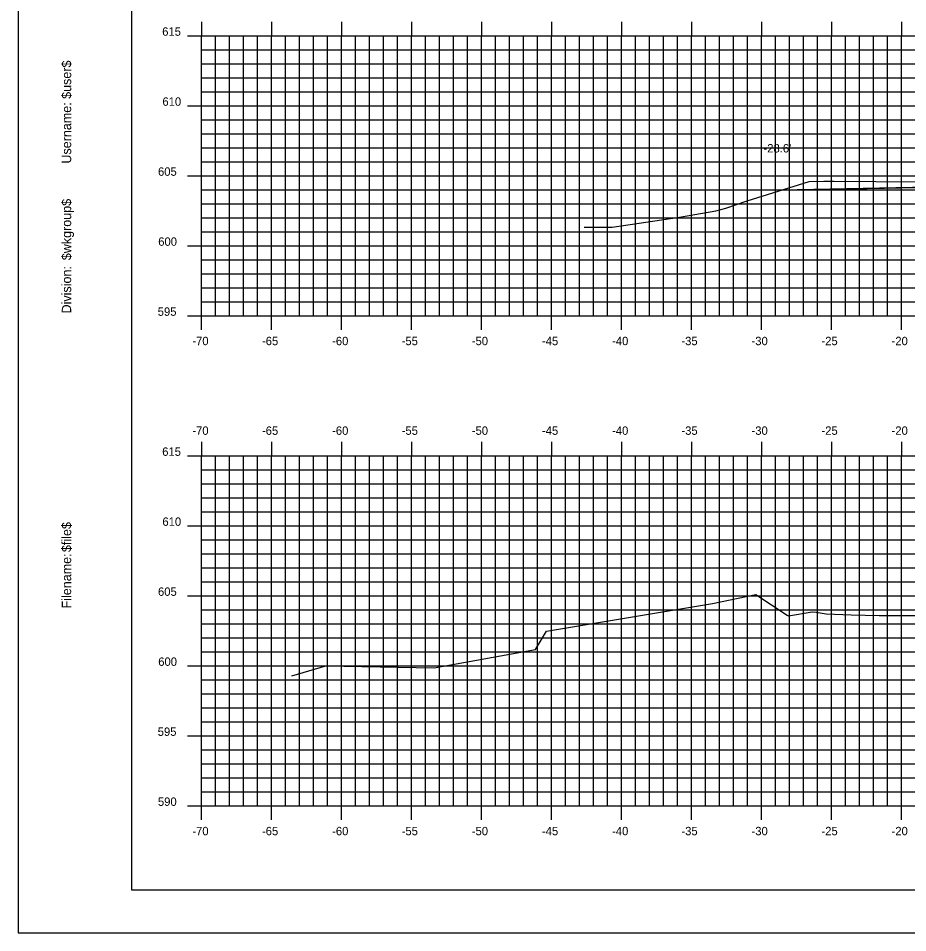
# Model space of a CAD drawing. Extents: x 1048362 to 1048532, y 780904 to 781014.
# Drawn here: x 1048362.4 to 1048425.9, y 780904.1 to 780969.4 of the extents above; entities that cross this region are included whole.
import ezdxf

# ---------------------------------------------------------------- set-up
doc = ezdxf.new("R2010")
doc.units = 0
for name, color, linetype in [('ANNOTATION', 7, 'Continuous'), ('D_Roadway_Centerline', 7, 'Continuous'), ('D_Roadway_SlopeLines', 7, 'Continuous'), ('Default', 7, 'Continuous'), ('H_V ANNOTATION', 7, 'Continuous'), ('MAJOR', 7, 'Continuous'), ('MINOR', 7, 'Continuous'), ('S_Roadway_Centerline', 7, 'Continuous')]:
    doc.layers.add(name, color=color, linetype=linetype)

msp = doc.modelspace()

# ---------------------------------------------------------------- linework, layer by layer
at = {"layer": 'D_Roadway_Centerline'}
msp.add_lwpolyline([(1048416.852, 780957.079), (1048434.112, 780957.424), (1048445.469, 780957.651), (1048479.364, 780956.973), (1048491.458, 780956.731)], dxfattribs=at)
at = {"layer": 'D_Roadway_SlopeLines'}
msp.add_line((1048434.112, 780957.424), (1048416.852, 780957.079), dxfattribs=at)
at = {"layer": 'Default'}
for p, q in [((1048370.47, 781012.114), (1048370.47, 780907.114)), ((1048370.47, 780907.114), (1048530.47, 780907.114))]:
    msp.add_line(p, q, dxfattribs=at)
msp.add_lwpolyline([(1048362.376, 780904.055), (1048532.376, 780904.055), (1048532.376, 781014.055), (1048362.376, 781014.055)], close=True, dxfattribs=at)
at = {"layer": 'MAJOR'}
for p, q in [((1048375.469, 780969.116), (1048375.469, 780968.114)), ((1048380.469, 780969.116), (1048380.469, 780968.114)), ((1048385.469, 780969.116), (1048385.469, 780968.114)), ((1048390.469, 780969.116), (1048390.469, 780968.114)), ((1048395.469, 780969.116), (1048395.469, 780968.114)), ((1048400.469, 780969.116), (1048400.469, 780968.114)), ((1048405.469, 780969.116), (1048405.469, 780968.114)), ((1048410.469, 780969.116), (1048410.469, 780968.114)), ((1048415.469, 780969.116), (1048415.469, 780968.114)), ((1048420.469, 780969.116), (1048420.469, 780968.114)), ((1048425.469, 780969.116), (1048425.469, 780968.114)), ((1048374.467, 780968.114), (1048375.469, 780968.114)), ((1048375.469, 780968.114), (1048515.469, 780968.114)), ((1048375.469, 780948.114), (1048375.469, 780968.114)), ((1048375.469, 780948.114), (1048375.469, 780968.114)), ((1048375.469, 780968.114), (1048515.469, 780968.114)), ((1048380.469, 780948.114), (1048380.469, 780968.114)), ((1048385.469, 780948.114), (1048385.469, 780968.114)), ((1048390.469, 780948.114), (1048390.469, 780968.114)), ((1048395.469, 780948.114), (1048395.469, 780968.114)), ((1048400.469, 780948.114), (1048400.469, 780968.114)), ((1048405.469, 780948.114), (1048405.469, 780968.114)), ((1048410.469, 780948.114), (1048410.469, 780968.114)), ((1048415.469, 780948.114), (1048415.469, 780968.114)), ((1048420.469, 780948.114), (1048420.469, 780968.114)), ((1048425.469, 780948.114), (1048425.469, 780968.114)), ((1048374.467, 780963.114), (1048375.469, 780963.114)), ((1048375.469, 780963.114), (1048515.469, 780963.114)), ((1048374.467, 780958.114), (1048375.469, 780958.114)), ((1048375.469, 780958.114), (1048515.469, 780958.114)), ((1048374.467, 780953.114), (1048375.469, 780953.114)), ((1048375.469, 780953.114), (1048515.469, 780953.114)), ((1048374.467, 780948.114), (1048375.469, 780948.114)), ((1048375.469, 780948.114), (1048515.469, 780948.114)), ((1048375.469, 780948.114), (1048515.469, 780948.114)), ((1048375.469, 780947.112), (1048375.469, 780948.114)), ((1048380.469, 780947.112), (1048380.469, 780948.114)), ((1048385.469, 780947.112), (1048385.469, 780948.114)), ((1048390.469, 780947.112), (1048390.469, 780948.114)), ((1048395.469, 780947.112), (1048395.469, 780948.114)), ((1048400.469, 780947.112), (1048400.469, 780948.114)), ((1048405.469, 780947.112), (1048405.469, 780948.114)), ((1048410.469, 780947.112), (1048410.469, 780948.114)), ((1048415.469, 780947.112), (1048415.469, 780948.114)), ((1048420.469, 780947.112), (1048420.469, 780948.114)), ((1048425.469, 780947.112), (1048425.469, 780948.114)), ((1048375.469, 780939.116), (1048375.469, 780938.114)), ((1048380.469, 780939.116), (1048380.469, 780938.114)), ((1048385.469, 780939.116), (1048385.469, 780938.114)), ((1048390.469, 780939.116), (1048390.469, 780938.114)), ((1048395.469, 780939.116), (1048395.469, 780938.114)), ((1048400.469, 780939.116), (1048400.469, 780938.114)), ((1048405.469, 780939.116), (1048405.469, 780938.114)), ((1048410.469, 780939.116), (1048410.469, 780938.114)), ((1048415.469, 780939.116), (1048415.469, 780938.114)), ((1048420.469, 780939.116), (1048420.469, 780938.114)), ((1048425.469, 780939.116), (1048425.469, 780938.114)), ((1048374.467, 780938.114), (1048375.469, 780938.114)), ((1048375.469, 780938.114), (1048515.469, 780938.114)), ((1048375.469, 780913.114), (1048375.469, 780938.114)), ((1048375.469, 780913.114), (1048375.469, 780938.114)), ((1048375.469, 780938.114), (1048515.469, 780938.114)), ((1048380.469, 780913.114), (1048380.469, 780938.114)), ((1048385.469, 780913.114), (1048385.469, 780938.114)), ((1048390.469, 780913.114), (1048390.469, 780938.114)), ((1048395.469, 780913.114), (1048395.469, 780938.114)), ((1048400.469, 780913.114), (1048400.469, 780938.114)), ((1048405.469, 780913.114), (1048405.469, 780938.114)), ((1048410.469, 780913.114), (1048410.469, 780938.114)), ((1048415.469, 780913.114), (1048415.469, 780938.114)), ((1048420.469, 780913.114), (1048420.469, 780938.114)), ((1048425.469, 780913.114), (1048425.469, 780938.114)), ((1048374.467, 780933.114), (1048375.469, 780933.114)), ((1048375.469, 780933.114), (1048515.469, 780933.114)), ((1048374.467, 780928.114), (1048375.469, 780928.114)), ((1048375.469, 780928.114), (1048515.469, 780928.114)), ((1048374.467, 780923.114), (1048375.469, 780923.114)), ((1048375.469, 780923.114), (1048515.469, 780923.114)), ((1048374.467, 780918.114), (1048375.469, 780918.114)), ((1048375.469, 780918.114), (1048515.469, 780918.114)), ((1048374.467, 780913.114), (1048375.469, 780913.114)), ((1048375.469, 780913.114), (1048515.469, 780913.114)), ((1048375.469, 780913.114), (1048515.469, 780913.114)), ((1048375.469, 780912.112), (1048375.469, 780913.114)), ((1048380.469, 780912.112), (1048380.469, 780913.114)), ((1048385.469, 780912.112), (1048385.469, 780913.114)), ((1048390.469, 780912.112), (1048390.469, 780913.114)), ((1048395.469, 780912.112), (1048395.469, 780913.114)), ((1048400.469, 780912.112), (1048400.469, 780913.114)), ((1048405.469, 780912.112), (1048405.469, 780913.114)), ((1048410.469, 780912.112), (1048410.469, 780913.114)), ((1048415.469, 780912.112), (1048415.469, 780913.114)), ((1048420.469, 780912.112), (1048420.469, 780913.114)), ((1048425.469, 780912.112), (1048425.469, 780913.114))]:
    msp.add_line(p, q, dxfattribs=at)
at = {"layer": 'MINOR'}
for p, q in [((1048376.469, 780948.114), (1048376.469, 780968.114)), ((1048377.469, 780948.114), (1048377.469, 780968.114)), ((1048378.469, 780948.114), (1048378.469, 780968.114)), ((1048379.469, 780948.114), (1048379.469, 780968.114)), ((1048381.469, 780948.114), (1048381.469, 780968.114)), ((1048382.469, 780948.114), (1048382.469, 780968.114)), ((1048383.469, 780948.114), (1048383.469, 780968.114)), ((1048384.469, 780948.114), (1048384.469, 780968.114)), ((1048386.469, 780948.114), (1048386.469, 780968.114)), ((1048387.469, 780948.114), (1048387.469, 780968.114)), ((1048388.469, 780948.114), (1048388.469, 780968.114)), ((1048389.469, 780948.114), (1048389.469, 780968.114)), ((1048391.469, 780948.114), (1048391.469, 780968.114)), ((1048392.469, 780948.114), (1048392.469, 780968.114)), ((1048393.469, 780948.114), (1048393.469, 780968.114)), ((1048394.469, 780948.114), (1048394.469, 780968.114)), ((1048396.469, 780948.114), (1048396.469, 780968.114)), ((1048397.469, 780948.114), (1048397.469, 780968.114)), ((1048398.469, 780948.114), (1048398.469, 780968.114)), ((1048399.469, 780948.114), (1048399.469, 780968.114)), ((1048401.469, 780948.114), (1048401.469, 780968.114)), ((1048402.469, 780948.114), (1048402.469, 780968.114)), ((1048403.469, 780948.114), (1048403.469, 780968.114)), ((1048404.469, 780948.114), (1048404.469, 780968.114)), ((1048406.469, 780948.114), (1048406.469, 780968.114)), ((1048407.469, 780948.114), (1048407.469, 780968.114)), ((1048408.469, 780948.114), (1048408.469, 780968.114)), ((1048409.469, 780948.114), (1048409.469, 780968.114)), ((1048411.469, 780948.114), (1048411.469, 780968.114)), ((1048412.469, 780948.114), (1048412.469, 780968.114)), ((1048413.469, 780948.114), (1048413.469, 780968.114)), ((1048414.469, 780948.114), (1048414.469, 780968.114)), ((1048416.469, 780948.114), (1048416.469, 780968.114)), ((1048417.469, 780948.114), (1048417.469, 780968.114)), ((1048418.469, 780948.114), (1048418.469, 780968.114)), ((1048419.469, 780948.114), (1048419.469, 780968.114)), ((1048421.469, 780948.114), (1048421.469, 780968.114)), ((1048422.469, 780948.114), (1048422.469, 780968.114)), ((1048423.469, 780948.114), (1048423.469, 780968.114)), ((1048424.469, 780948.114), (1048424.469, 780968.114)), ((1048375.469, 780967.114), (1048515.469, 780967.114)), ((1048375.469, 780967.114), (1048376.471, 780967.114)), ((1048375.469, 780966.114), (1048515.469, 780966.114)), ((1048375.469, 780966.114), (1048376.471, 780966.114)), ((1048375.469, 780965.114), (1048515.469, 780965.114)), ((1048375.469, 780965.114), (1048376.471, 780965.114)), ((1048375.469, 780964.114), (1048515.469, 780964.114)), ((1048375.469, 780964.114), (1048376.471, 780964.114)), ((1048375.469, 780962.114), (1048515.469, 780962.114)), ((1048375.469, 780962.114), (1048376.471, 780962.114)), ((1048375.469, 780961.114), (1048515.469, 780961.114)), ((1048375.469, 780961.114), (1048376.471, 780961.114)), ((1048375.469, 780960.114), (1048515.469, 780960.114)), ((1048375.469, 780960.114), (1048376.471, 780960.114)), ((1048375.469, 780959.114), (1048515.469, 780959.114)), ((1048375.469, 780959.114), (1048376.471, 780959.114)), ((1048375.469, 780957.114), (1048515.469, 780957.114)), ((1048375.469, 780957.114), (1048376.471, 780957.114)), ((1048375.469, 780956.114), (1048515.469, 780956.114)), ((1048375.469, 780956.114), (1048376.471, 780956.114)), ((1048375.469, 780955.114), (1048515.469, 780955.114)), ((1048375.469, 780955.114), (1048376.471, 780955.114)), ((1048375.469, 780954.114), (1048515.469, 780954.114)), ((1048375.469, 780954.114), (1048376.471, 780954.114)), ((1048375.469, 780952.114), (1048515.469, 780952.114)), ((1048375.469, 780952.114), (1048376.471, 780952.114)), ((1048375.469, 780951.114), (1048515.469, 780951.114)), ((1048375.469, 780951.114), (1048376.471, 780951.114)), ((1048375.469, 780950.114), (1048515.469, 780950.114)), ((1048375.469, 780950.114), (1048376.471, 780950.114)), ((1048375.469, 780949.114), (1048515.469, 780949.114)), ((1048375.469, 780949.114), (1048376.471, 780949.114)), ((1048376.469, 780913.114), (1048376.469, 780938.114)), ((1048377.469, 780913.114), (1048377.469, 780938.114)), ((1048378.469, 780913.114), (1048378.469, 780938.114)), ((1048379.469, 780913.114), (1048379.469, 780938.114)), ((1048381.469, 780913.114), (1048381.469, 780938.114)), ((1048382.469, 780913.114), (1048382.469, 780938.114)), ((1048383.469, 780913.114), (1048383.469, 780938.114)), ((1048384.469, 780913.114), (1048384.469, 780938.114)), ((1048386.469, 780913.114), (1048386.469, 780938.114)), ((1048387.469, 780913.114), (1048387.469, 780938.114)), ((1048388.469, 780913.114), (1048388.469, 780938.114)), ((1048389.469, 780913.114), (1048389.469, 780938.114)), ((1048391.469, 780913.114), (1048391.469, 780938.114)), ((1048392.469, 780913.114), (1048392.469, 780938.114)), ((1048393.469, 780913.114), (1048393.469, 780938.114)), ((1048394.469, 780913.114), (1048394.469, 780938.114)), ((1048396.469, 780913.114), (1048396.469, 780938.114)), ((1048397.469, 780913.114), (1048397.469, 780938.114)), ((1048398.469, 780913.114), (1048398.469, 780938.114)), ((1048399.469, 780913.114), (1048399.469, 780938.114)), ((1048401.469, 780913.114), (1048401.469, 780938.114)), ((1048402.469, 780913.114), (1048402.469, 780938.114)), ((1048403.469, 780913.114), (1048403.469, 780938.114)), ((1048404.469, 780913.114), (1048404.469, 780938.114)), ((1048406.469, 780913.114), (1048406.469, 780938.114)), ((1048407.469, 780913.114), (1048407.469, 780938.114)), ((1048408.469, 780913.114), (1048408.469, 780938.114)), ((1048409.469, 780913.114), (1048409.469, 780938.114)), ((1048411.469, 780913.114), (1048411.469, 780938.114)), ((1048412.469, 780913.114), (1048412.469, 780938.114)), ((1048413.469, 780913.114), (1048413.469, 780938.114)), ((1048414.469, 780913.114), (1048414.469, 780938.114)), ((1048416.469, 780913.114), (1048416.469, 780938.114)), ((1048417.469, 780913.114), (1048417.469, 780938.114)), ((1048418.469, 780913.114), (1048418.469, 780938.114)), ((1048419.469, 780913.114), (1048419.469, 780938.114)), ((1048421.469, 780913.114), (1048421.469, 780938.114)), ((1048422.469, 780913.114), (1048422.469, 780938.114)), ((1048423.469, 780913.114), (1048423.469, 780938.114)), ((1048424.469, 780913.114), (1048424.469, 780938.114)), ((1048375.469, 780937.114), (1048515.469, 780937.114)), ((1048375.469, 780937.114), (1048376.471, 780937.114)), ((1048375.469, 780936.114), (1048515.469, 780936.114)), ((1048375.469, 780936.114), (1048376.471, 780936.114)), ((1048375.469, 780935.114), (1048515.469, 780935.114)), ((1048375.469, 780935.114), (1048376.471, 780935.114)), ((1048375.469, 780934.114), (1048515.469, 780934.114)), ((1048375.469, 780934.114), (1048376.471, 780934.114)), ((1048375.469, 780932.114), (1048515.469, 780932.114)), ((1048375.469, 780932.114), (1048376.471, 780932.114)), ((1048375.469, 780931.114), (1048515.469, 780931.114)), ((1048375.469, 780931.114), (1048376.471, 780931.114)), ((1048375.469, 780930.114), (1048515.469, 780930.114)), ((1048375.469, 780930.114), (1048376.471, 780930.114)), ((1048375.469, 780929.114), (1048515.469, 780929.114)), ((1048375.469, 780929.114), (1048376.471, 780929.114)), ((1048375.469, 780927.114), (1048515.469, 780927.114)), ((1048375.469, 780927.114), (1048376.471, 780927.114)), ((1048375.469, 780926.114), (1048515.469, 780926.114)), ((1048375.469, 780926.114), (1048376.471, 780926.114)), ((1048375.469, 780925.114), (1048515.469, 780925.114)), ((1048375.469, 780925.114), (1048376.471, 780925.114)), ((1048375.469, 780924.114), (1048515.469, 780924.114)), ((1048375.469, 780924.114), (1048376.471, 780924.114)), ((1048375.469, 780922.114), (1048515.469, 780922.114)), ((1048375.469, 780922.114), (1048376.471, 780922.114)), ((1048375.469, 780921.114), (1048515.469, 780921.114)), ((1048375.469, 780921.114), (1048376.471, 780921.114)), ((1048375.469, 780920.114), (1048515.469, 780920.114)), ((1048375.469, 780920.114), (1048376.471, 780920.114)), ((1048375.469, 780919.114), (1048515.469, 780919.114)), ((1048375.469, 780919.114), (1048376.471, 780919.114)), ((1048375.469, 780917.114), (1048515.469, 780917.114)), ((1048375.469, 780917.114), (1048376.471, 780917.114)), ((1048375.469, 780916.114), (1048515.469, 780916.114)), ((1048375.469, 780916.114), (1048376.471, 780916.114)), ((1048375.469, 780915.114), (1048515.469, 780915.114)), ((1048375.469, 780915.114), (1048376.471, 780915.114)), ((1048375.469, 780914.114), (1048515.469, 780914.114)), ((1048375.469, 780914.114), (1048376.471, 780914.114))]:
    msp.add_line(p, q, dxfattribs=at)
at = {"layer": 'S_Roadway_Centerline'}
for points in [[(1048402.812, 780954.442), (1048404.804, 780954.45), (1048409.616, 780955.164), (1048412.21, 780955.603), (1048412.919, 780955.793), (1048414.449, 780956.32), (1048418.872, 780957.716), (1048419.922, 780957.738), (1048420.632, 780957.738), (1048426.629, 780957.671)], [(1048381.907, 780922.399), (1048384.341, 780923.121), (1048392.098, 780922.968), (1048399.32, 780924.282), (1048400.11, 780925.587), (1048411.977, 780927.555), (1048415.055, 780928.209), (1048417.302, 780926.738), (1048417.41, 780926.682), (1048419.097, 780926.972), (1048419.377, 780926.941), (1048420.099, 780926.828), (1048421.879, 780926.746), (1048423.875, 780926.711), (1048429.061, 780926.707)]]:
    msp.add_lwpolyline(points, dxfattribs=at)

# ---------------------------------------------------------------- texts
at = {"layer": 'ANNOTATION'}
msp.add_text("-28.6'", height=0.6, rotation=360, dxfattribs=at).set_placement((1048415.613, 780959.779))
at = {"layer": 'Default'}
for s, p in [('$user$', (1048366.155, 780963.606)), ('Username:', (1048366.155, 780958.982)), ('$wkgroup$', (1048366.155, 780952.084)), ('Division:', (1048366.155, 780948.28)), ('$file$', (1048366.155, 780931.24)), ('Filename:', (1048366.155, 780927.213))]:
    msp.add_text(s, height=0.6696, rotation=90, dxfattribs=at).set_placement(p)
at = {"layer": 'H_V ANNOTATION'}
for s, p in [('615', (1048372.658, 780968.114)), ('610', (1048372.674, 780963.114)), ('605', (1048372.358, 780958.114)), ('600', (1048372.374, 780953.114)), ('595', (1048372.337, 780948.114)), ('-70', (1048374.811, 780946.014)), ('-65', (1048379.787, 780946.014)), ('-60', (1048384.795, 780946.014)), ('-55', (1048389.766, 780946.014)), ('-50', (1048394.774, 780946.014)), ('-45', (1048399.787, 780946.014)), ('-40', (1048404.795, 780946.014)), ('-35', (1048409.75, 780946.014)), ('-30', (1048414.758, 780946.014)), ('-25', (1048419.755, 780946.014)), ('-20', (1048424.763, 780946.014)), ('-70', (1048374.811, 780939.614)), ('-65', (1048379.787, 780939.614)), ('-60', (1048384.795, 780939.614)), ('-55', (1048389.766, 780939.614)), ('-50', (1048394.774, 780939.614)), ('-45', (1048399.787, 780939.614)), ('-40', (1048404.795, 780939.614)), ('-35', (1048409.75, 780939.614)), ('-30', (1048414.758, 780939.614)), ('-25', (1048419.755, 780939.614)), ('-20', (1048424.763, 780939.614)), ('615', (1048372.658, 780938.114)), ('610', (1048372.674, 780933.114)), ('605', (1048372.358, 780928.114)), ('600', (1048372.374, 780923.114)), ('595', (1048372.337, 780918.114)), ('590', (1048372.353, 780913.114)), ('-70', (1048374.811, 780911.014)), ('-65', (1048379.787, 780911.014)), ('-60', (1048384.795, 780911.014)), ('-55', (1048389.766, 780911.014)), ('-50', (1048394.774, 780911.014)), ('-45', (1048399.787, 780911.014)), ('-40', (1048404.795, 780911.014)), ('-35', (1048409.75, 780911.014)), ('-30', (1048414.758, 780911.014)), ('-25', (1048419.755, 780911.014)), ('-20', (1048424.763, 780911.014))]:
    msp.add_text(s, height=0.6, dxfattribs=at).set_placement(p)
at = {"layer": 'MAJOR'}
for p in [(1048375.465, 780948.114), (1048375.465, 780913.114)]:
    msp.add_text('-', height=0.006, dxfattribs=at).set_placement(p)

doc.saveas('drawing.dxf')
